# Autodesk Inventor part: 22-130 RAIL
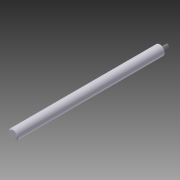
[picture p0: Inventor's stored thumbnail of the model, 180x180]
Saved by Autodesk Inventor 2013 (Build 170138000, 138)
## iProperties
Created: 2004-11
Part Number: 22-130 RAIL
Material: Aluminium - 6061
Document SubType Name: Modeling
Designer: Autodesk, Inc.
Manufacturer: Standard
Standards Organization: Custom
Description: BIN MOUNTING SLIDE RAIL
Catalog Web Link: http://www.parker.com/ead/cm1.asp?cmid=809
Vendor: PARKER IPS
Mass: 524.122 g
Surface Area: 317.4 cm^2
Volume: 193.403 cm^3
Density: 2.71 g/cm^3
CAGE: 1LJX3
Dept. ID: Product Design
Description #2: ---
Finish #1: ---
Finish #2: ---
Material ID: ---
Project Number: ---
Author: Autodesk, Inc.
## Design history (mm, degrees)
sketch "Sketch1"
  geometry: C1 r 12.7 at (0, 0)
  constraints: 1 centre point, 1 other
  dimensions: "d0" = 25.4 diameter of C1
extrude "Extrusion1" new body sketch "Sketch1" distance "d1" = 380; taper "d2" = 0 deg
sketch "Sketch2"
  geometry: C1 r 12.7 at (0, 0) reference; C2 r 4 at (0, 0)
  constraints: 1 centre point, 1 coincident
  dimensions: "d3" = 8 diameter of C2
extrude "Extrusion2" join sketch "Sketch2" distance "d4" = 20; taper "d5" = 0 deg
thread "Thread1" dims "d6" = 10, "d7" = 0
chamfer "Chamfer1" distance "d8" = 2; stored, may be unused: second distance "d9" = 2, angle "d10" = 45 deg
body "Solid1"
